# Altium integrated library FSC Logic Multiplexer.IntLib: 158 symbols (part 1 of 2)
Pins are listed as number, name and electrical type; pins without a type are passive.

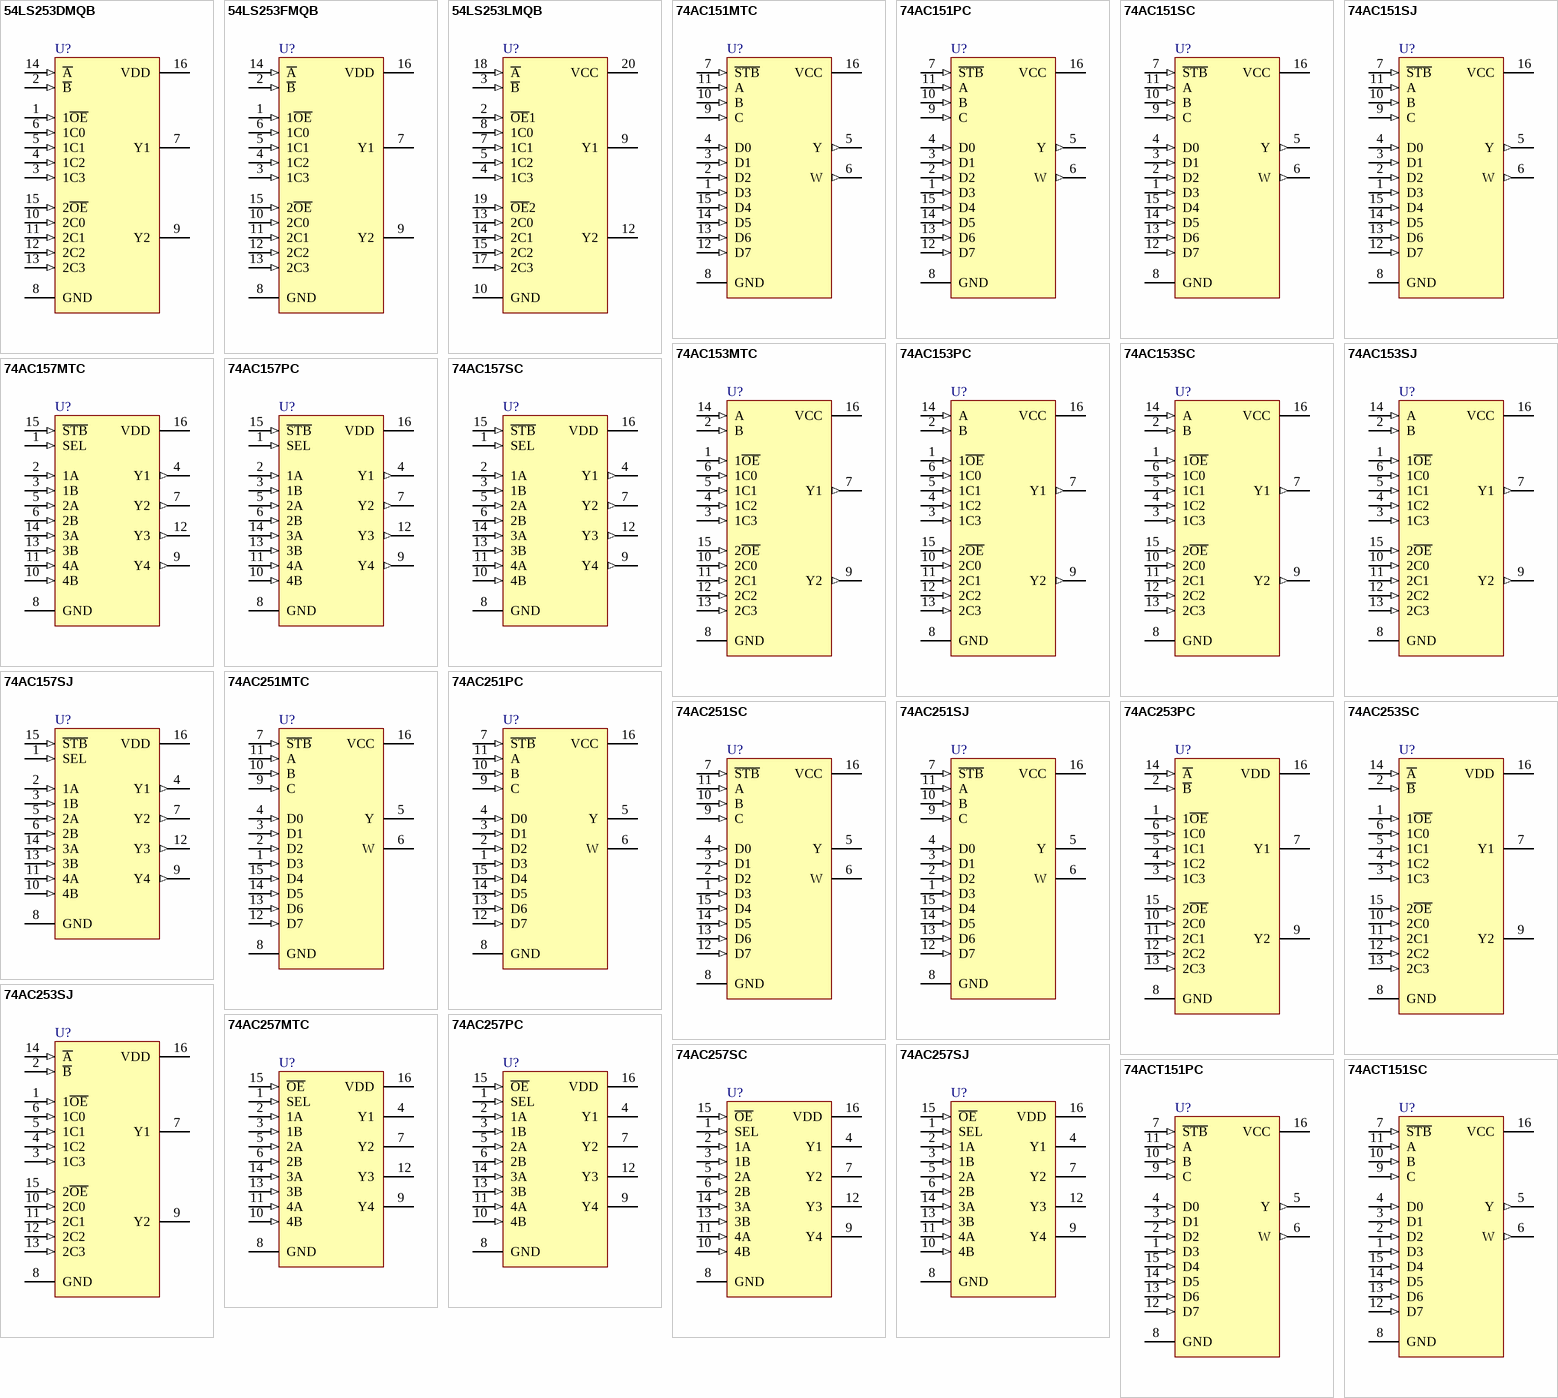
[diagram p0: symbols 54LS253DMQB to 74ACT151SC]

## 54LS253DMQB
designator U?
3-State Data Selector/Multiplexer; Note: Generic simulation model provided.
footprint J16A (DIP, 16-Leads, Row Spacing 7.62mm, Pitch 2.54mm, Body 19.56x6.73mm)
3D model N16E (CerDIP, 16-Pin, Row Spacing 7.62 mm, Pitch 2.54 mm)
simulation model 74LS253 (SIMCODE)
signal-integrity model 54LS253DMQB
pins: 1 1~{OE} (in), 2 ~{B} (in), 3 1C3 (in), 4 1C2 (in), 5 1C1 (in), 6 1C0 (in), 7 Y1 (hiz), 8 GND (power), 9 Y2 (hiz), 10 2C0 (in), 11 2C1 (in), 12 2C2 (in), 13 2C3 (in), 14 ~{A} (in), 15 2~{OE} (in), 16 VDD (power)

## 54LS253FMQB
designator U?
3-State Data Selector/Multiplexer; Note: Generic simulation model provided.
footprint W16A (DFP; 16 Leads; Body 9.9 x 7.6 mm (LxW max); Pitch 1.27 mm)
3D model W16A (DFP; 16 Leads; Body 9.9 x 7.6 mm (LxW max); Pitch 1.27 mm)
simulation model 74LS253 (SIMCODE)
signal-integrity model 54LS253FMQB
pins: 1 1~{OE} (in), 2 ~{B} (in), 3 1C3 (in), 4 1C2 (in), 5 1C1 (in), 6 1C0 (in), 7 Y1 (hiz), 8 GND (power), 9 Y2 (hiz), 10 2C0 (in), 11 2C1 (in), 12 2C2 (in), 13 2C3 (in), 14 ~{A} (in), 15 2~{OE} (in), 16 VDD (power)

## 54LS253LMQB
designator U?
3-State Data Selector/Multiplexer; Note: Pins 1, 6, 11 and 16 are not connected and not drawn.
footprint E20A (Leadless Chip Carrier; 20 Terminals; Body 8.9 x 8.9 mm)
footprint E20A_N (Leadless Chip Carrier, 20-Leads, Body 8.9x8.9mm, Pitch 1.27mm, IPC Medium Density)
footprint E20A_L (Leadless Chip Carrier, 20-Leads, Body 8.9x8.9mm, Pitch 1.27mm, IPC High Density)
footprint E20A_M (Leadless Chip Carrier, 20-Leads, Body 8.9x8.9mm, Pitch 1.27mm, IPC Low Density)
simulation model 74LS253 (SIMCODE)
signal-integrity model 54LS253LMQB
pins: 2 ~{OE}1 (in), 3 ~{B} (in), 4 1C3 (in), 5 1C2 (in), 7 1C1 (in), 8 1C0 (in), 9 Y1 (hiz), 10 GND (power), 12 Y2 (hiz), 13 2C0 (in), 14 2C1 (in), 15 2C2 (in), 17 2C3 (in), 18 ~{A} (in), 19 ~{OE}2 (in), 20 VCC (power)

## 74AC151MTC
designator U?
8-Input Multiplexer
footprint MTC16_N (TSOP, 16-Leads, Body 5x4.4mm, Pitch 0.65mm, IPC Medium Density)
footprint MTC16_L (TSOP, 16-Leads, Body 5x4.4mm, Pitch 0.65mm, IPC High Density)
footprint MTC16_M (TSOP, 16-Leads, Body 5x4.4mm, Pitch 0.65mm, IPC Low Density)
3D model MTC16 (16-Pin Thin Small Outline Package 0.65 mm Pitch)
signal-integrity model 74AC151MTC
pins: 1 D3 (in), 2 D2 (in), 3 D1 (in), 4 D0 (in), 5 Y (out), 6 W (out), 7 ~{STB} (in), 8 GND (power), 9 C (in), 10 B (in), 11 A (in), 12 D7 (in), 13 D6 (in), 14 D5 (in), 15 D4 (in), 16 VCC (power)

## 74AC151PC
designator U?
8-Input Multiplexer
footprint N16E (DIP, 16-Leads, Row Spacing 7.62mm, Pitch 2.54mm, Body 19.3x6.35mm)
3D model N16E (DIP, 16-Pin, Row Spacing 7.62 mm, Pitch 2.54 mm)
signal-integrity model 74AC151PC
pins: 1 D3 (in), 2 D2 (in), 3 D1 (in), 4 D0 (in), 5 Y (out), 6 W (out), 7 ~{STB} (in), 8 GND (power), 9 C (in), 10 B (in), 11 A (in), 12 D7 (in), 13 D6 (in), 14 D5 (in), 15 D4 (in), 16 VCC (power)

## 74AC151SC
designator U?
8-Input Multiplexer
footprint M16A_N (SOIC, 16-Leads, Body 9.9x3.9mm, Pitch 1.27mm, IPC Medium Density)
footprint M16A_L (SOIC, 16-Leads, Body 9.9x3.9mm, Pitch 1.27mm, IPC High Density)
footprint M16A_M (SOIC, 16-Leads, Body 9.9x3.9mm, Pitch 1.27mm, IPC Low Density)
3D model M16A (16-Pin Small Outline Integrated Circuit 1.27 mm Pitch)
signal-integrity model 74AC151SC
pins: 1 D3 (in), 2 D2 (in), 3 D1 (in), 4 D0 (in), 5 Y (out), 6 W (out), 7 ~{STB} (in), 8 GND (power), 9 C (in), 10 B (in), 11 A (in), 12 D7 (in), 13 D6 (in), 14 D5 (in), 15 D4 (in), 16 VCC (power)

## 74AC151SJ
designator U?
8-Input Multiplexer
footprint M16D_N (SOP, 16-Leads, Body 10.1x5.3mm, Pitch 1.27mm, IPC Medium Density)
footprint M16D_L (SOP, 16-Leads, Body 10.1x5.3mm, Pitch 1.27mm, IPC High Density)
footprint M16D_M (SOP, 16-Leads, Body 10.1x5.3mm, Pitch 1.27mm, IPC Low Density)
3D model M16D (16-Pin Small Outline Package 1.27 mm Pitch)
signal-integrity model 74AC151SJ
pins: 1 D3 (in), 2 D2 (in), 3 D1 (in), 4 D0 (in), 5 Y (out), 6 W (out), 7 ~{STB} (in), 8 GND (power), 9 C (in), 10 B (in), 11 A (in), 12 D7 (in), 13 D6 (in), 14 D5 (in), 15 D4 (in), 16 VCC (power)

## 74AC153MTC
designator U?
Dual 4-Input Multiplexer
footprint MTC16_N (TSOP, 16-Leads, Body 5x4.4mm, Pitch 0.65mm, IPC Medium Density)
footprint MTC16_L (TSOP, 16-Leads, Body 5x4.4mm, Pitch 0.65mm, IPC High Density)
footprint MTC16_M (TSOP, 16-Leads, Body 5x4.4mm, Pitch 0.65mm, IPC Low Density)
3D model MTC16 (16-Pin Thin Small Outline Package 0.65 mm Pitch)
signal-integrity model 74AC153MTC
pins: 1 1~{OE} (in), 2 B (in), 3 1C3 (in), 4 1C2 (in), 5 1C1 (in), 6 1C0 (in), 7 Y1 (out), 8 GND (power), 9 Y2 (out), 10 2C0 (in), 11 2C1 (in), 12 2C2 (in), 13 2C3 (in), 14 A (in), 15 2~{OE} (in), 16 VCC (power)

## 74AC153PC
designator U?
Dual 4-Input Multiplexer
footprint N16E (DIP, 16-Leads, Row Spacing 7.62mm, Pitch 2.54mm, Body 19.3x6.35mm)
3D model N16E (DIP, 16-Pin, Row Spacing 7.62 mm, Pitch 2.54 mm)
signal-integrity model 74AC153PC
pins: 1 1~{OE} (in), 2 B (in), 3 1C3 (in), 4 1C2 (in), 5 1C1 (in), 6 1C0 (in), 7 Y1 (out), 8 GND (power), 9 Y2 (out), 10 2C0 (in), 11 2C1 (in), 12 2C2 (in), 13 2C3 (in), 14 A (in), 15 2~{OE} (in), 16 VCC (power)

## 74AC153SC
designator U?
Dual 4-Input Multiplexer
footprint M16A_N (SOIC, 16-Leads, Body 9.9x3.9mm, Pitch 1.27mm, IPC Medium Density)
footprint M16A_L (SOIC, 16-Leads, Body 9.9x3.9mm, Pitch 1.27mm, IPC High Density)
footprint M16A_M (SOIC, 16-Leads, Body 9.9x3.9mm, Pitch 1.27mm, IPC Low Density)
3D model M16A (16-Pin Small Outline Integrated Circuit 1.27 mm Pitch)
signal-integrity model 74AC153SC
pins: 1 1~{OE} (in), 2 B (in), 3 1C3 (in), 4 1C2 (in), 5 1C1 (in), 6 1C0 (in), 7 Y1 (out), 8 GND (power), 9 Y2 (out), 10 2C0 (in), 11 2C1 (in), 12 2C2 (in), 13 2C3 (in), 14 A (in), 15 2~{OE} (in), 16 VCC (power)

## 74AC153SJ
designator U?
Dual 4-Input Multiplexer
footprint M16D_N (SOP, 16-Leads, Body 10.1x5.3mm, Pitch 1.27mm, IPC Medium Density)
footprint M16D_L (SOP, 16-Leads, Body 10.1x5.3mm, Pitch 1.27mm, IPC High Density)
footprint M16D_M (SOP, 16-Leads, Body 10.1x5.3mm, Pitch 1.27mm, IPC Low Density)
3D model M16D (16-Pin Small Outline Package 1.27 mm Pitch)
signal-integrity model 74AC153SJ
pins: 1 1~{OE} (in), 2 B (in), 3 1C3 (in), 4 1C2 (in), 5 1C1 (in), 6 1C0 (in), 7 Y1 (out), 8 GND (power), 9 Y2 (out), 10 2C0 (in), 11 2C1 (in), 12 2C2 (in), 13 2C3 (in), 14 A (in), 15 2~{OE} (in), 16 VCC (power)

## 74AC157MTC
designator U?
Quad 2-Input Multiplexer
footprint MTC16_N (TSOP, 16-Leads, Body 5x4.4mm, Pitch 0.65mm, IPC Medium Density)
footprint MTC16_L (TSOP, 16-Leads, Body 5x4.4mm, Pitch 0.65mm, IPC High Density)
footprint MTC16_M (TSOP, 16-Leads, Body 5x4.4mm, Pitch 0.65mm, IPC Low Density)
3D model MTC16 (16-Pin Thin Small Outline Package 0.65 mm Pitch)
signal-integrity model 74AC157MTC
pins: 1 SEL (in), 2 1A (in), 3 1B (in), 4 Y1 (out), 5 2A (in), 6 2B (in), 7 Y2 (out), 8 GND (power), 9 Y4 (out), 10 4B (in), 11 4A (in), 12 Y3 (out), 13 3B (in), 14 3A (in), 15 ~{STB} (in), 16 VDD (power)

## 74AC157PC
designator U?
Quad 2-Input Multiplexer
footprint N16E (DIP, 16-Leads, Row Spacing 7.62mm, Pitch 2.54mm, Body 19.3x6.35mm)
3D model N16E (DIP, 16-Pin, Row Spacing 7.62 mm, Pitch 2.54 mm)
signal-integrity model 74AC157PC
pins: 1 SEL (in), 2 1A (in), 3 1B (in), 4 Y1 (out), 5 2A (in), 6 2B (in), 7 Y2 (out), 8 GND (power), 9 Y4 (out), 10 4B (in), 11 4A (in), 12 Y3 (out), 13 3B (in), 14 3A (in), 15 ~{STB} (in), 16 VDD (power)

## 74AC157SC
designator U?
Quad 2-Input Multiplexer
footprint M16A_N (SOIC, 16-Leads, Body 9.9x3.9mm, Pitch 1.27mm, IPC Medium Density)
footprint M16A_L (SOIC, 16-Leads, Body 9.9x3.9mm, Pitch 1.27mm, IPC High Density)
footprint M16A_M (SOIC, 16-Leads, Body 9.9x3.9mm, Pitch 1.27mm, IPC Low Density)
3D model M16A (16-Pin Small Outline Integrated Circuit 1.27 mm Pitch)
signal-integrity model 74AC157SC
pins: 1 SEL (in), 2 1A (in), 3 1B (in), 4 Y1 (out), 5 2A (in), 6 2B (in), 7 Y2 (out), 8 GND (power), 9 Y4 (out), 10 4B (in), 11 4A (in), 12 Y3 (out), 13 3B (in), 14 3A (in), 15 ~{STB} (in), 16 VDD (power)

## 74AC157SJ
designator U?
Quad 2-Input Multiplexer
footprint M16D_N (SOP, 16-Leads, Body 10.1x5.3mm, Pitch 1.27mm, IPC Medium Density)
footprint M16D_L (SOP, 16-Leads, Body 10.1x5.3mm, Pitch 1.27mm, IPC High Density)
footprint M16D_M (SOP, 16-Leads, Body 10.1x5.3mm, Pitch 1.27mm, IPC Low Density)
3D model M16D (16-Pin Small Outline Package 1.27 mm Pitch)
signal-integrity model 74AC157SJ
pins: 1 SEL (in), 2 1A (in), 3 1B (in), 4 Y1 (out), 5 2A (in), 6 2B (in), 7 Y2 (out), 8 GND (power), 9 Y4 (out), 10 4B (in), 11 4A (in), 12 Y3 (out), 13 3B (in), 14 3A (in), 15 ~{STB} (in), 16 VDD (power)

## 74AC251MTC
designator U?
8-Input Multiplexer with 3-State Output; Note: Generic simulation model provided.
footprint MTC16_N (TSOP, 16-Leads, Body 5x4.4mm, Pitch 0.65mm, IPC Medium Density)
footprint MTC16_L (TSOP, 16-Leads, Body 5x4.4mm, Pitch 0.65mm, IPC High Density)
footprint MTC16_M (TSOP, 16-Leads, Body 5x4.4mm, Pitch 0.65mm, IPC Low Density)
3D model MTC16 (16-Pin Thin Small Outline Package 0.65 mm Pitch)
simulation model 74LS251 (SIMCODE)
signal-integrity model 74AC251MTC
pins: 1 D3 (in), 2 D2 (in), 3 D1 (in), 4 D0 (in), 5 Y (hiz), 6 W (hiz), 7 ~{STB} (in), 8 GND (power), 9 C (in), 10 B (in), 11 A (in), 12 D7 (in), 13 D6 (in), 14 D5 (in), 15 D4 (in), 16 VCC (power)

## 74AC251PC
designator U?
8-Input Multiplexer with 3-State Output; Note: Generic simulation model provided.
footprint N16E (DIP, 16-Leads, Row Spacing 7.62mm, Pitch 2.54mm, Body 19.3x6.35mm)
3D model N16E (DIP, 16-Pin, Row Spacing 7.62 mm, Pitch 2.54 mm)
simulation model 74LS251 (SIMCODE)
signal-integrity model 74AC251PC
pins: 1 D3 (in), 2 D2 (in), 3 D1 (in), 4 D0 (in), 5 Y (hiz), 6 W (hiz), 7 ~{STB} (in), 8 GND (power), 9 C (in), 10 B (in), 11 A (in), 12 D7 (in), 13 D6 (in), 14 D5 (in), 15 D4 (in), 16 VCC (power)

## 74AC251SC
designator U?
8-Input Multiplexer with 3-State Output; Note: Generic simulation model provided.
footprint M16A_N (SOIC, 16-Leads, Body 9.9x3.9mm, Pitch 1.27mm, IPC Medium Density)
footprint M16A_L (SOIC, 16-Leads, Body 9.9x3.9mm, Pitch 1.27mm, IPC High Density)
footprint M16A_M (SOIC, 16-Leads, Body 9.9x3.9mm, Pitch 1.27mm, IPC Low Density)
3D model M16A (16-Pin Small Outline Integrated Circuit 1.27 mm Pitch)
simulation model 74LS251 (SIMCODE)
signal-integrity model 74AC251SC
pins: 1 D3 (in), 2 D2 (in), 3 D1 (in), 4 D0 (in), 5 Y (hiz), 6 W (hiz), 7 ~{STB} (in), 8 GND (power), 9 C (in), 10 B (in), 11 A (in), 12 D7 (in), 13 D6 (in), 14 D5 (in), 15 D4 (in), 16 VCC (power)

## 74AC251SJ
designator U?
8-Input Multiplexer with 3-State Output; Note: Generic simulation model provided.
footprint M16D_N (SOP, 16-Leads, Body 10.1x5.3mm, Pitch 1.27mm, IPC Medium Density)
footprint M16D_L (SOP, 16-Leads, Body 10.1x5.3mm, Pitch 1.27mm, IPC High Density)
footprint M16D_M (SOP, 16-Leads, Body 10.1x5.3mm, Pitch 1.27mm, IPC Low Density)
3D model M16D (16-Pin Small Outline Package 1.27 mm Pitch)
simulation model 74LS251 (SIMCODE)
signal-integrity model 74AC251SJ
pins: 1 D3 (in), 2 D2 (in), 3 D1 (in), 4 D0 (in), 5 Y (hiz), 6 W (hiz), 7 ~{STB} (in), 8 GND (power), 9 C (in), 10 B (in), 11 A (in), 12 D7 (in), 13 D6 (in), 14 D5 (in), 15 D4 (in), 16 VCC (power)

## 74AC253PC
designator U?
Dual 4-Input Multiplexer with 3-State Outputs
footprint N16E (DIP, 16-Leads, Row Spacing 7.62mm, Pitch 2.54mm, Body 19.3x6.35mm)
3D model N16E (DIP, 16-Pin, Row Spacing 7.62 mm, Pitch 2.54 mm)
signal-integrity model 74AC253PC
pins: 1 1~{OE} (in), 2 ~{B} (in), 3 1C3 (in), 4 1C2 (in), 5 1C1 (in), 6 1C0 (in), 7 Y1 (hiz), 8 GND (power), 9 Y2 (hiz), 10 2C0 (in), 11 2C1 (in), 12 2C2 (in), 13 2C3 (in), 14 ~{A} (in), 15 2~{OE} (in), 16 VDD (power)

## 74AC253SC
designator U?
Dual 4-Input Multiplexer with 3-State Outputs
footprint M16A_N (SOIC, 16-Leads, Body 9.9x3.9mm, Pitch 1.27mm, IPC Medium Density)
footprint M16A_L (SOIC, 16-Leads, Body 9.9x3.9mm, Pitch 1.27mm, IPC High Density)
footprint M16A_M (SOIC, 16-Leads, Body 9.9x3.9mm, Pitch 1.27mm, IPC Low Density)
3D model M16A (16-Pin Small Outline Integrated Circuit 1.27 mm Pitch)
signal-integrity model 74AC253SC
pins: 1 1~{OE} (in), 2 ~{B} (in), 3 1C3 (in), 4 1C2 (in), 5 1C1 (in), 6 1C0 (in), 7 Y1 (hiz), 8 GND (power), 9 Y2 (hiz), 10 2C0 (in), 11 2C1 (in), 12 2C2 (in), 13 2C3 (in), 14 ~{A} (in), 15 2~{OE} (in), 16 VDD (power)

## 74AC253SJ
designator U?
Dual 4-Input Multiplexer with 3-State Outputs
footprint M16D_N (SOP, 16-Leads, Body 10.1x5.3mm, Pitch 1.27mm, IPC Medium Density)
footprint M16D_L (SOP, 16-Leads, Body 10.1x5.3mm, Pitch 1.27mm, IPC High Density)
footprint M16D_M (SOP, 16-Leads, Body 10.1x5.3mm, Pitch 1.27mm, IPC Low Density)
3D model M16D (16-Pin Small Outline Package 1.27 mm Pitch)
signal-integrity model 74AC253SJ
pins: 1 1~{OE} (in), 2 ~{B} (in), 3 1C3 (in), 4 1C2 (in), 5 1C1 (in), 6 1C0 (in), 7 Y1 (hiz), 8 GND (power), 9 Y2 (hiz), 10 2C0 (in), 11 2C1 (in), 12 2C2 (in), 13 2C3 (in), 14 ~{A} (in), 15 2~{OE} (in), 16 VDD (power)

## 74AC257MTC
designator U?
Quad 2-Input Multiplexer with 3-State Outputs
footprint MTC16_N (TSOP, 16-Leads, Body 5x4.4mm, Pitch 0.65mm, IPC Medium Density)
footprint MTC16_L (TSOP, 16-Leads, Body 5x4.4mm, Pitch 0.65mm, IPC High Density)
footprint MTC16_M (TSOP, 16-Leads, Body 5x4.4mm, Pitch 0.65mm, IPC Low Density)
3D model MTC16 (16-Pin Thin Small Outline Package 0.65 mm Pitch)
signal-integrity model 74AC257MTC
pins: 1 SEL (in), 2 1A (in), 3 1B (in), 4 Y1 (hiz), 5 2A (in), 6 2B (in), 7 Y2 (hiz), 8 GND (power), 9 Y4 (hiz), 10 4B (in), 11 4A (in), 12 Y3 (hiz), 13 3B (in), 14 3A (in), 15 ~{OE} (in), 16 VDD (power)

## 74AC257PC
designator U?
Quad 2-Input Multiplexer with 3-State Outputs
footprint N16E (DIP, 16-Leads, Row Spacing 7.62mm, Pitch 2.54mm, Body 19.3x6.35mm)
3D model N16E (DIP, 16-Pin, Row Spacing 7.62 mm, Pitch 2.54 mm)
signal-integrity model 74AC257PC
pins: 1 SEL (in), 2 1A (in), 3 1B (in), 4 Y1 (hiz), 5 2A (in), 6 2B (in), 7 Y2 (hiz), 8 GND (power), 9 Y4 (hiz), 10 4B (in), 11 4A (in), 12 Y3 (hiz), 13 3B (in), 14 3A (in), 15 ~{OE} (in), 16 VDD (power)

## 74AC257SC
designator U?
Quad 2-Input Multiplexer with 3-State Outputs
footprint M16A_N (SOIC, 16-Leads, Body 9.9x3.9mm, Pitch 1.27mm, IPC Medium Density)
footprint M16A_L (SOIC, 16-Leads, Body 9.9x3.9mm, Pitch 1.27mm, IPC High Density)
footprint M16A_M (SOIC, 16-Leads, Body 9.9x3.9mm, Pitch 1.27mm, IPC Low Density)
3D model M16A (16-Pin Small Outline Integrated Circuit 1.27 mm Pitch)
signal-integrity model 74AC257SC
pins: 1 SEL (in), 2 1A (in), 3 1B (in), 4 Y1 (hiz), 5 2A (in), 6 2B (in), 7 Y2 (hiz), 8 GND (power), 9 Y4 (hiz), 10 4B (in), 11 4A (in), 12 Y3 (hiz), 13 3B (in), 14 3A (in), 15 ~{OE} (in), 16 VDD (power)

## 74AC257SJ
designator U?
Quad 2-Input Multiplexer with 3-State Outputs
footprint M16D_N (SOP, 16-Leads, Body 10.1x5.3mm, Pitch 1.27mm, IPC Medium Density)
footprint M16D_L (SOP, 16-Leads, Body 10.1x5.3mm, Pitch 1.27mm, IPC High Density)
footprint M16D_M (SOP, 16-Leads, Body 10.1x5.3mm, Pitch 1.27mm, IPC Low Density)
3D model M16D (16-Pin Small Outline Package 1.27 mm Pitch)
signal-integrity model 74AC257SJ
pins: 1 SEL (in), 2 1A (in), 3 1B (in), 4 Y1 (hiz), 5 2A (in), 6 2B (in), 7 Y2 (hiz), 8 GND (power), 9 Y4 (hiz), 10 4B (in), 11 4A (in), 12 Y3 (hiz), 13 3B (in), 14 3A (in), 15 ~{OE} (in), 16 VDD (power)

## 74ACT151PC
designator U?
8-Input Multiplexer
footprint N16E (DIP, 16-Leads, Row Spacing 7.62mm, Pitch 2.54mm, Body 19.3x6.35mm)
3D model N16E (DIP, 16-Pin, Row Spacing 7.62 mm, Pitch 2.54 mm)
signal-integrity model 74ACT151PC
pins: 1 D3 (in), 2 D2 (in), 3 D1 (in), 4 D0 (in), 5 Y (out), 6 W (out), 7 ~{STB} (in), 8 GND (power), 9 C (in), 10 B (in), 11 A (in), 12 D7 (in), 13 D6 (in), 14 D5 (in), 15 D4 (in), 16 VCC (power)

## 74ACT151SC
designator U?
8-Input Multiplexer
footprint M16A_N (SOIC, 16-Leads, Body 9.9x3.9mm, Pitch 1.27mm, IPC Medium Density)
footprint M16A_L (SOIC, 16-Leads, Body 9.9x3.9mm, Pitch 1.27mm, IPC High Density)
footprint M16A_M (SOIC, 16-Leads, Body 9.9x3.9mm, Pitch 1.27mm, IPC Low Density)
3D model M16A (16-Pin Small Outline Integrated Circuit 1.27 mm Pitch)
signal-integrity model 74ACT151SC
pins: 1 D3 (in), 2 D2 (in), 3 D1 (in), 4 D0 (in), 5 Y (out), 6 W (out), 7 ~{STB} (in), 8 GND (power), 9 C (in), 10 B (in), 11 A (in), 12 D7 (in), 13 D6 (in), 14 D5 (in), 15 D4 (in), 16 VCC (power)

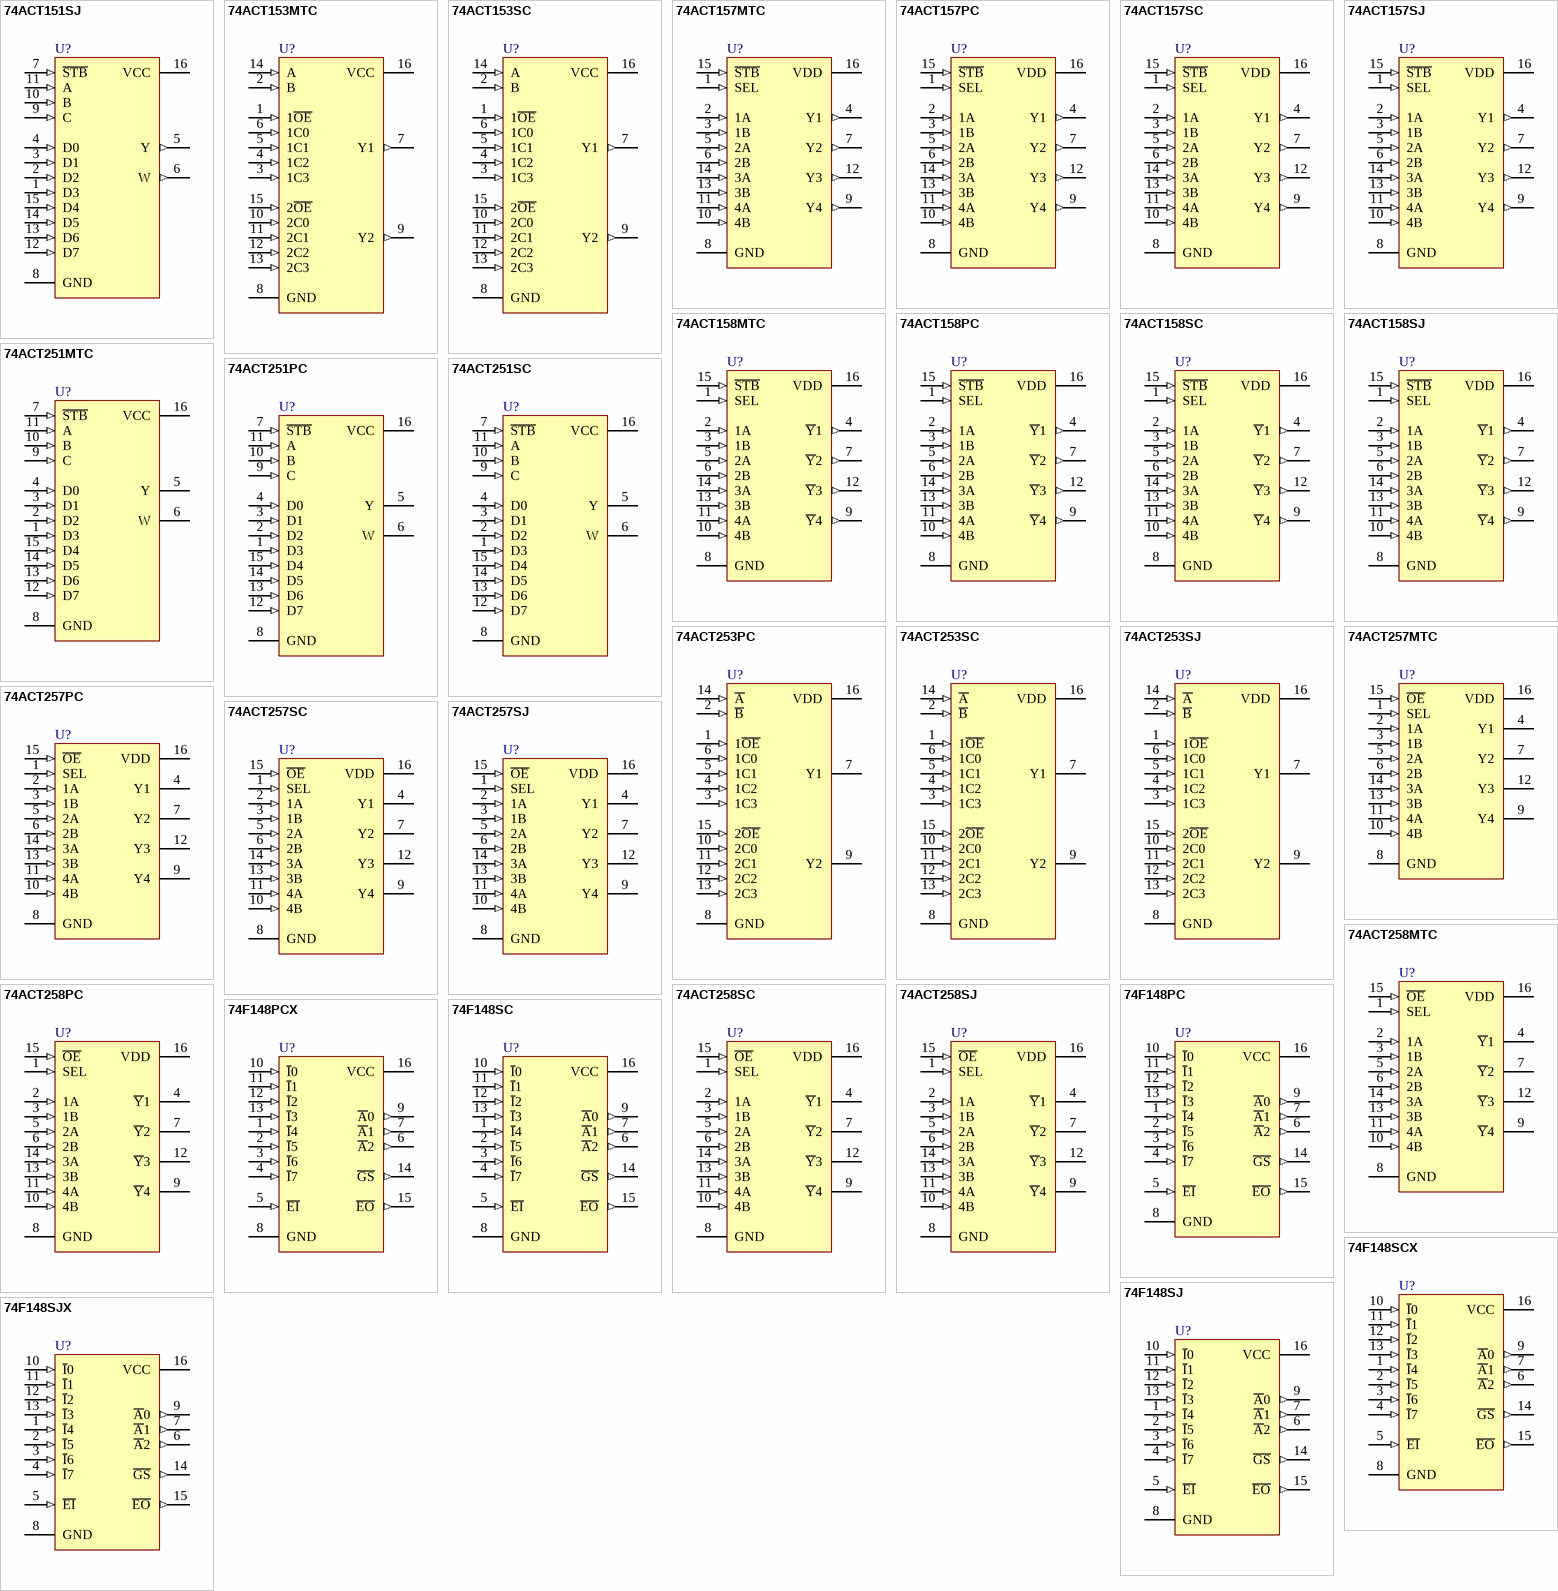
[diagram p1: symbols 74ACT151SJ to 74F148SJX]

## 74ACT151SJ
designator U?
8-Input Multiplexer
footprint M16D_N (SOP, 16-Leads, Body 10.1x5.3mm, Pitch 1.27mm, IPC Medium Density)
footprint M16D_L (SOP, 16-Leads, Body 10.1x5.3mm, Pitch 1.27mm, IPC High Density)
footprint M16D_M (SOP, 16-Leads, Body 10.1x5.3mm, Pitch 1.27mm, IPC Low Density)
3D model M16D (16-Pin Small Outline Package 1.27 mm Pitch)
signal-integrity model 74ACT151SJ
pins: 1 D3 (in), 2 D2 (in), 3 D1 (in), 4 D0 (in), 5 Y (out), 6 W (out), 7 ~{STB} (in), 8 GND (power), 9 C (in), 10 B (in), 11 A (in), 12 D7 (in), 13 D6 (in), 14 D5 (in), 15 D4 (in), 16 VCC (power)

## 74ACT153MTC
designator U?
Dual 4-Input Multiplexer
footprint MTC16_N (TSOP, 16-Leads, Body 5x4.4mm, Pitch 0.65mm, IPC Medium Density)
footprint MTC16_L (TSOP, 16-Leads, Body 5x4.4mm, Pitch 0.65mm, IPC High Density)
footprint MTC16_M (TSOP, 16-Leads, Body 5x4.4mm, Pitch 0.65mm, IPC Low Density)
3D model MTC16 (16-Pin Thin Small Outline Package 0.65 mm Pitch)
signal-integrity model 74ACT153MTC
pins: 1 1~{OE} (in), 2 B (in), 3 1C3 (in), 4 1C2 (in), 5 1C1 (in), 6 1C0 (in), 7 Y1 (out), 8 GND (power), 9 Y2 (out), 10 2C0 (in), 11 2C1 (in), 12 2C2 (in), 13 2C3 (in), 14 A (in), 15 2~{OE} (in), 16 VCC (power)

## 74ACT153SC
designator U?
Dual 4-Input Multiplexer
footprint M16A_N (SOIC, 16-Leads, Body 9.9x3.9mm, Pitch 1.27mm, IPC Medium Density)
footprint M16A_L (SOIC, 16-Leads, Body 9.9x3.9mm, Pitch 1.27mm, IPC High Density)
footprint M16A_M (SOIC, 16-Leads, Body 9.9x3.9mm, Pitch 1.27mm, IPC Low Density)
3D model M16A (16-Pin Small Outline Integrated Circuit 1.27 mm Pitch)
signal-integrity model 74ACT153SC
pins: 1 1~{OE} (in), 2 B (in), 3 1C3 (in), 4 1C2 (in), 5 1C1 (in), 6 1C0 (in), 7 Y1 (out), 8 GND (power), 9 Y2 (out), 10 2C0 (in), 11 2C1 (in), 12 2C2 (in), 13 2C3 (in), 14 A (in), 15 2~{OE} (in), 16 VCC (power)

## 74ACT157MTC
designator U?
Quad 2-Input Multiplexer
footprint MTC16_N (TSOP, 16-Leads, Body 5x4.4mm, Pitch 0.65mm, IPC Medium Density)
footprint MTC16_L (TSOP, 16-Leads, Body 5x4.4mm, Pitch 0.65mm, IPC High Density)
footprint MTC16_M (TSOP, 16-Leads, Body 5x4.4mm, Pitch 0.65mm, IPC Low Density)
3D model MTC16 (16-Pin Thin Small Outline Package 0.65 mm Pitch)
signal-integrity model 74ACT157MTC
pins: 1 SEL (in), 2 1A (in), 3 1B (in), 4 Y1 (out), 5 2A (in), 6 2B (in), 7 Y2 (out), 8 GND (power), 9 Y4 (out), 10 4B (in), 11 4A (in), 12 Y3 (out), 13 3B (in), 14 3A (in), 15 ~{STB} (in), 16 VDD (power)

## 74ACT157PC
designator U?
Quad 2-Input Multiplexer
footprint N16E (DIP, 16-Leads, Row Spacing 7.62mm, Pitch 2.54mm, Body 19.3x6.35mm)
3D model N16E (DIP, 16-Pin, Row Spacing 7.62 mm, Pitch 2.54 mm)
signal-integrity model 74ACT157PC
pins: 1 SEL (in), 2 1A (in), 3 1B (in), 4 Y1 (out), 5 2A (in), 6 2B (in), 7 Y2 (out), 8 GND (power), 9 Y4 (out), 10 4B (in), 11 4A (in), 12 Y3 (out), 13 3B (in), 14 3A (in), 15 ~{STB} (in), 16 VDD (power)

## 74ACT157SC
designator U?
Quad 2-Input Multiplexer
footprint M16A_N (SOIC, 16-Leads, Body 9.9x3.9mm, Pitch 1.27mm, IPC Medium Density)
footprint M16A_L (SOIC, 16-Leads, Body 9.9x3.9mm, Pitch 1.27mm, IPC High Density)
footprint M16A_M (SOIC, 16-Leads, Body 9.9x3.9mm, Pitch 1.27mm, IPC Low Density)
3D model M16A (16-Pin Small Outline Integrated Circuit 1.27 mm Pitch)
signal-integrity model 74ACT157SC
pins: 1 SEL (in), 2 1A (in), 3 1B (in), 4 Y1 (out), 5 2A (in), 6 2B (in), 7 Y2 (out), 8 GND (power), 9 Y4 (out), 10 4B (in), 11 4A (in), 12 Y3 (out), 13 3B (in), 14 3A (in), 15 ~{STB} (in), 16 VDD (power)

## 74ACT157SJ
designator U?
Quad 2-Input Multiplexer
footprint M16D_N (SOP, 16-Leads, Body 10.1x5.3mm, Pitch 1.27mm, IPC Medium Density)
footprint M16D_L (SOP, 16-Leads, Body 10.1x5.3mm, Pitch 1.27mm, IPC High Density)
footprint M16D_M (SOP, 16-Leads, Body 10.1x5.3mm, Pitch 1.27mm, IPC Low Density)
3D model M16D (16-Pin Small Outline Package 1.27 mm Pitch)
signal-integrity model 74ACT157SJ
pins: 1 SEL (in), 2 1A (in), 3 1B (in), 4 Y1 (out), 5 2A (in), 6 2B (in), 7 Y2 (out), 8 GND (power), 9 Y4 (out), 10 4B (in), 11 4A (in), 12 Y3 (out), 13 3B (in), 14 3A (in), 15 ~{STB} (in), 16 VDD (power)

## 74ACT158MTC
designator U?
Quad 2-Input Multiplexer; Note: Generic simulation model provided.
footprint MTC16_N (TSOP, 16-Leads, Body 5x4.4mm, Pitch 0.65mm, IPC Medium Density)
footprint MTC16_L (TSOP, 16-Leads, Body 5x4.4mm, Pitch 0.65mm, IPC High Density)
footprint MTC16_M (TSOP, 16-Leads, Body 5x4.4mm, Pitch 0.65mm, IPC Low Density)
3D model MTC16 (16-Pin Thin Small Outline Package 0.65 mm Pitch)
simulation model 74LS158 (SIMCODE)
signal-integrity model 74ACT158MTC
pins: 1 SEL (in), 2 1A (in), 3 1B (in), 4 ~{Y}1 (out), 5 2A (in), 6 2B (in), 7 ~{Y}2 (out), 8 GND (power), 9 ~{Y}4 (out), 10 4B (in), 11 4A (in), 12 ~{Y}3 (out), 13 3B (in), 14 3A (in), 15 ~{STB} (in), 16 VDD (power)

## 74ACT158PC
designator U?
Quad 2-Input Multiplexer; Note: Generic simulation model provided.
footprint M16D_N (SOP, 16-Leads, Body 10.1x5.3mm, Pitch 1.27mm, IPC Medium Density)
footprint M16D_L (SOP, 16-Leads, Body 10.1x5.3mm, Pitch 1.27mm, IPC High Density)
footprint M16D_M (SOP, 16-Leads, Body 10.1x5.3mm, Pitch 1.27mm, IPC Low Density)
3D model M16D (16-Pin Small Outline Package 1.27 mm Pitch)
simulation model 74LS158 (SIMCODE)
signal-integrity model 74ACT158PC
pins: 1 SEL (in), 2 1A (in), 3 1B (in), 4 ~{Y}1 (out), 5 2A (in), 6 2B (in), 7 ~{Y}2 (out), 8 GND (power), 9 ~{Y}4 (out), 10 4B (in), 11 4A (in), 12 ~{Y}3 (out), 13 3B (in), 14 3A (in), 15 ~{STB} (in), 16 VDD (power)

## 74ACT158SC
designator U?
Quad 2-Input Multiplexer; Note: Generic simulation model provided.
footprint M16A_N (SOIC, 16-Leads, Body 9.9x3.9mm, Pitch 1.27mm, IPC Medium Density)
footprint M16A_L (SOIC, 16-Leads, Body 9.9x3.9mm, Pitch 1.27mm, IPC High Density)
footprint M16A_M (SOIC, 16-Leads, Body 9.9x3.9mm, Pitch 1.27mm, IPC Low Density)
3D model M16A (16-Pin Small Outline Integrated Circuit 1.27 mm Pitch)
simulation model 74LS158 (SIMCODE)
signal-integrity model 74ACT158SC
pins: 1 SEL (in), 2 1A (in), 3 1B (in), 4 ~{Y}1 (out), 5 2A (in), 6 2B (in), 7 ~{Y}2 (out), 8 GND (power), 9 ~{Y}4 (out), 10 4B (in), 11 4A (in), 12 ~{Y}3 (out), 13 3B (in), 14 3A (in), 15 ~{STB} (in), 16 VDD (power)

## 74ACT158SJ
designator U?
Quad 2-Input Multiplexer; Note: Generic simulation model provided.
footprint N16E (DIP, 16-Leads, Row Spacing 7.62mm, Pitch 2.54mm, Body 19.3x6.35mm)
3D model N16E (DIP, 16-Pin, Row Spacing 7.62 mm, Pitch 2.54 mm)
simulation model 74LS158 (SIMCODE)
signal-integrity model 74ACT158SJ
pins: 1 SEL (in), 2 1A (in), 3 1B (in), 4 ~{Y}1 (out), 5 2A (in), 6 2B (in), 7 ~{Y}2 (out), 8 GND (power), 9 ~{Y}4 (out), 10 4B (in), 11 4A (in), 12 ~{Y}3 (out), 13 3B (in), 14 3A (in), 15 ~{STB} (in), 16 VDD (power)

## 74ACT251MTC
designator U?
8-Input Multiplexer with 3-State Output; Note: Generic simulation model provided.
footprint MTC16_N (TSOP, 16-Leads, Body 5x4.4mm, Pitch 0.65mm, IPC Medium Density)
footprint MTC16_L (TSOP, 16-Leads, Body 5x4.4mm, Pitch 0.65mm, IPC High Density)
footprint MTC16_M (TSOP, 16-Leads, Body 5x4.4mm, Pitch 0.65mm, IPC Low Density)
3D model MTC16 (16-Pin Thin Small Outline Package 0.65 mm Pitch)
simulation model 74LS251 (SIMCODE)
signal-integrity model 74ACT251MTC
pins: 1 D3 (in), 2 D2 (in), 3 D1 (in), 4 D0 (in), 5 Y (hiz), 6 W (hiz), 7 ~{STB} (in), 8 GND (power), 9 C (in), 10 B (in), 11 A (in), 12 D7 (in), 13 D6 (in), 14 D5 (in), 15 D4 (in), 16 VCC (power)

## 74ACT251PC
designator U?
8-Input Multiplexer with 3-State Output; Note: Generic simulation model provided.
footprint N16E (DIP, 16-Leads, Row Spacing 7.62mm, Pitch 2.54mm, Body 19.3x6.35mm)
3D model N16E (DIP, 16-Pin, Row Spacing 7.62 mm, Pitch 2.54 mm)
simulation model 74LS251 (SIMCODE)
signal-integrity model 74ACT251PC
pins: 1 D3 (in), 2 D2 (in), 3 D1 (in), 4 D0 (in), 5 Y (hiz), 6 W (hiz), 7 ~{STB} (in), 8 GND (power), 9 C (in), 10 B (in), 11 A (in), 12 D7 (in), 13 D6 (in), 14 D5 (in), 15 D4 (in), 16 VCC (power)

## 74ACT251SC
designator U?
8-Input Multiplexer with 3-State Output; Note: Generic simulation model provided.
footprint M16A_N (SOIC, 16-Leads, Body 9.9x3.9mm, Pitch 1.27mm, IPC Medium Density)
footprint M16A_L (SOIC, 16-Leads, Body 9.9x3.9mm, Pitch 1.27mm, IPC High Density)
footprint M16A_M (SOIC, 16-Leads, Body 9.9x3.9mm, Pitch 1.27mm, IPC Low Density)
3D model M16A (16-Pin Small Outline Integrated Circuit 1.27 mm Pitch)
simulation model 74LS251 (SIMCODE)
signal-integrity model 74ACT251SC
pins: 1 D3 (in), 2 D2 (in), 3 D1 (in), 4 D0 (in), 5 Y (hiz), 6 W (hiz), 7 ~{STB} (in), 8 GND (power), 9 C (in), 10 B (in), 11 A (in), 12 D7 (in), 13 D6 (in), 14 D5 (in), 15 D4 (in), 16 VCC (power)

## 74ACT253PC
designator U?
Dual 4-Input Multiplexer with 3-State Outputs
footprint N16E (DIP, 16-Leads, Row Spacing 7.62mm, Pitch 2.54mm, Body 19.3x6.35mm)
3D model N16E (DIP, 16-Pin, Row Spacing 7.62 mm, Pitch 2.54 mm)
signal-integrity model 74ACT253PC
pins: 1 1~{OE} (in), 2 ~{B} (in), 3 1C3 (in), 4 1C2 (in), 5 1C1 (in), 6 1C0 (in), 7 Y1 (hiz), 8 GND (power), 9 Y2 (hiz), 10 2C0 (in), 11 2C1 (in), 12 2C2 (in), 13 2C3 (in), 14 ~{A} (in), 15 2~{OE} (in), 16 VDD (power)

## 74ACT253SC
designator U?
Dual 4-Input Multiplexer with 3-State Outputs
footprint M16A_N (SOIC, 16-Leads, Body 9.9x3.9mm, Pitch 1.27mm, IPC Medium Density)
footprint M16A_L (SOIC, 16-Leads, Body 9.9x3.9mm, Pitch 1.27mm, IPC High Density)
footprint M16A_M (SOIC, 16-Leads, Body 9.9x3.9mm, Pitch 1.27mm, IPC Low Density)
3D model M16A (16-Pin Small Outline Integrated Circuit 1.27 mm Pitch)
signal-integrity model 74ACT253SC
pins: 1 1~{OE} (in), 2 ~{B} (in), 3 1C3 (in), 4 1C2 (in), 5 1C1 (in), 6 1C0 (in), 7 Y1 (hiz), 8 GND (power), 9 Y2 (hiz), 10 2C0 (in), 11 2C1 (in), 12 2C2 (in), 13 2C3 (in), 14 ~{A} (in), 15 2~{OE} (in), 16 VDD (power)

## 74ACT253SJ
designator U?
Dual 4-Input Multiplexer with 3-State Outputs
footprint M16D_N (SOP, 16-Leads, Body 10.1x5.3mm, Pitch 1.27mm, IPC Medium Density)
footprint M16D_L (SOP, 16-Leads, Body 10.1x5.3mm, Pitch 1.27mm, IPC High Density)
footprint M16D_M (SOP, 16-Leads, Body 10.1x5.3mm, Pitch 1.27mm, IPC Low Density)
3D model M16D (16-Pin Small Outline Package 1.27 mm Pitch)
signal-integrity model 74ACT253SJ
pins: 1 1~{OE} (in), 2 ~{B} (in), 3 1C3 (in), 4 1C2 (in), 5 1C1 (in), 6 1C0 (in), 7 Y1 (hiz), 8 GND (power), 9 Y2 (hiz), 10 2C0 (in), 11 2C1 (in), 12 2C2 (in), 13 2C3 (in), 14 ~{A} (in), 15 2~{OE} (in), 16 VDD (power)

## 74ACT257MTC
designator U?
Quad 2-Input Multiplexer with 3-State Outputs
footprint MTC16_N (TSOP, 16-Leads, Body 5x4.4mm, Pitch 0.65mm, IPC Medium Density)
footprint MTC16_L (TSOP, 16-Leads, Body 5x4.4mm, Pitch 0.65mm, IPC High Density)
footprint MTC16_M (TSOP, 16-Leads, Body 5x4.4mm, Pitch 0.65mm, IPC Low Density)
3D model MTC16 (16-Pin Thin Small Outline Package 0.65 mm Pitch)
signal-integrity model 74ACT257MTC
pins: 1 SEL (in), 2 1A (in), 3 1B (in), 4 Y1 (hiz), 5 2A (in), 6 2B (in), 7 Y2 (hiz), 8 GND (power), 9 Y4 (hiz), 10 4B (in), 11 4A (in), 12 Y3 (hiz), 13 3B (in), 14 3A (in), 15 ~{OE} (in), 16 VDD (power)

## 74ACT257PC
designator U?
Quad 2-Input Multiplexer with 3-State Outputs
footprint N16E (DIP, 16-Leads, Row Spacing 7.62mm, Pitch 2.54mm, Body 19.3x6.35mm)
3D model N16E (DIP, 16-Pin, Row Spacing 7.62 mm, Pitch 2.54 mm)
signal-integrity model 74ACT257PC
pins: 1 SEL (in), 2 1A (in), 3 1B (in), 4 Y1 (hiz), 5 2A (in), 6 2B (in), 7 Y2 (hiz), 8 GND (power), 9 Y4 (hiz), 10 4B (in), 11 4A (in), 12 Y3 (hiz), 13 3B (in), 14 3A (in), 15 ~{OE} (in), 16 VDD (power)

## 74ACT257SC
designator U?
Quad 2-Input Multiplexer with 3-State Outputs
footprint M16A_N (SOIC, 16-Leads, Body 9.9x3.9mm, Pitch 1.27mm, IPC Medium Density)
footprint M16A_L (SOIC, 16-Leads, Body 9.9x3.9mm, Pitch 1.27mm, IPC High Density)
footprint M16A_M (SOIC, 16-Leads, Body 9.9x3.9mm, Pitch 1.27mm, IPC Low Density)
3D model M16A (16-Pin Small Outline Integrated Circuit 1.27 mm Pitch)
signal-integrity model 74ACT257SC
pins: 1 SEL (in), 2 1A (in), 3 1B (in), 4 Y1 (hiz), 5 2A (in), 6 2B (in), 7 Y2 (hiz), 8 GND (power), 9 Y4 (hiz), 10 4B (in), 11 4A (in), 12 Y3 (hiz), 13 3B (in), 14 3A (in), 15 ~{OE} (in), 16 VDD (power)

## 74ACT257SJ
designator U?
Quad 2-Input Multiplexer with 3-State Outputs
footprint M16D_N (SOP, 16-Leads, Body 10.1x5.3mm, Pitch 1.27mm, IPC Medium Density)
footprint M16D_L (SOP, 16-Leads, Body 10.1x5.3mm, Pitch 1.27mm, IPC High Density)
footprint M16D_M (SOP, 16-Leads, Body 10.1x5.3mm, Pitch 1.27mm, IPC Low Density)
3D model M16D (16-Pin Small Outline Package 1.27 mm Pitch)
signal-integrity model 74ACT257SJ
pins: 1 SEL (in), 2 1A (in), 3 1B (in), 4 Y1 (hiz), 5 2A (in), 6 2B (in), 7 Y2 (hiz), 8 GND (power), 9 Y4 (hiz), 10 4B (in), 11 4A (in), 12 Y3 (hiz), 13 3B (in), 14 3A (in), 15 ~{OE} (in), 16 VDD (power)

## 74ACT258MTC
designator U?
Quad 2-Input Multiplexer with 3-State Outputs
footprint MTC16_N (TSOP, 16-Leads, Body 5x4.4mm, Pitch 0.65mm, IPC Medium Density)
footprint MTC16_L (TSOP, 16-Leads, Body 5x4.4mm, Pitch 0.65mm, IPC High Density)
footprint MTC16_M (TSOP, 16-Leads, Body 5x4.4mm, Pitch 0.65mm, IPC Low Density)
3D model MTC16 (16-Pin Thin Small Outline Package 0.65 mm Pitch)
signal-integrity model 74ACT258MTC
pins: 1 SEL (in), 2 1A (in), 3 1B (in), 4 ~{Y}1 (hiz), 5 2A (in), 6 2B (in), 7 ~{Y}2 (hiz), 8 GND (power), 9 ~{Y}4 (hiz), 10 4B (in), 11 4A (in), 12 ~{Y}3 (hiz), 13 3B (in), 14 3A (in), 15 ~{OE} (in), 16 VDD (power)

## 74ACT258PC
designator U?
Quad 2-Input Multiplexer with 3-State Outputs
footprint N16E (DIP, 16-Leads, Row Spacing 7.62mm, Pitch 2.54mm, Body 19.3x6.35mm)
3D model N16E (DIP, 16-Pin, Row Spacing 7.62 mm, Pitch 2.54 mm)
signal-integrity model 74ACT258PC
pins: 1 SEL (in), 2 1A (in), 3 1B (in), 4 ~{Y}1 (hiz), 5 2A (in), 6 2B (in), 7 ~{Y}2 (hiz), 8 GND (power), 9 ~{Y}4 (hiz), 10 4B (in), 11 4A (in), 12 ~{Y}3 (hiz), 13 3B (in), 14 3A (in), 15 ~{OE} (in), 16 VDD (power)

## 74ACT258SC
designator U?
Quad 2-Input Multiplexer with 3-State Outputs
footprint M16A_N (SOIC, 16-Leads, Body 9.9x3.9mm, Pitch 1.27mm, IPC Medium Density)
footprint M16A_L (SOIC, 16-Leads, Body 9.9x3.9mm, Pitch 1.27mm, IPC High Density)
footprint M16A_M (SOIC, 16-Leads, Body 9.9x3.9mm, Pitch 1.27mm, IPC Low Density)
3D model M16A (16-Pin Small Outline Integrated Circuit 1.27 mm Pitch)
signal-integrity model 74ACT258SC
pins: 1 SEL (in), 2 1A (in), 3 1B (in), 4 ~{Y}1 (hiz), 5 2A (in), 6 2B (in), 7 ~{Y}2 (hiz), 8 GND (power), 9 ~{Y}4 (hiz), 10 4B (in), 11 4A (in), 12 ~{Y}3 (hiz), 13 3B (in), 14 3A (in), 15 ~{OE} (in), 16 VDD (power)

## 74ACT258SJ
designator U?
Quad 2-Input Multiplexer with 3-State Outputs
footprint M16D_N (SOP, 16-Leads, Body 10.1x5.3mm, Pitch 1.27mm, IPC Medium Density)
footprint M16D_L (SOP, 16-Leads, Body 10.1x5.3mm, Pitch 1.27mm, IPC High Density)
footprint M16D_M (SOP, 16-Leads, Body 10.1x5.3mm, Pitch 1.27mm, IPC Low Density)
3D model M16D (16-Pin Small Outline Package 1.27 mm Pitch)
signal-integrity model 74ACT258SJ
pins: 1 SEL (in), 2 1A (in), 3 1B (in), 4 ~{Y}1 (hiz), 5 2A (in), 6 2B (in), 7 ~{Y}2 (hiz), 8 GND (power), 9 ~{Y}4 (hiz), 10 4B (in), 11 4A (in), 12 ~{Y}3 (hiz), 13 3B (in), 14 3A (in), 15 ~{OE} (in), 16 VDD (power)

## 74F148PC
designator U?
8-Line to 3-Line Priority Encoder; Note: Generic simulation model provided.
footprint N16E (DIP, 16-Leads, Row Spacing 7.62mm, Pitch 2.54mm, Body 19.3x6.35mm)
3D model N16E (DIP, 16-Pin, Row Spacing 7.62 mm, Pitch 2.54 mm)
simulation model 74F148 (SIMCODE)
signal-integrity model 74F148PC
pins: 1 ~{I}4 (in), 2 ~{I}5 (in), 3 ~{I}6 (in), 4 ~{I}7 (in), 5 ~{EI} (in), 6 ~{A}2 (out), 7 ~{A}1 (out), 8 GND (power), 9 ~{A}0 (out), 10 ~{I}0 (in), 11 ~{I}1 (in), 12 ~{I}2 (in), 13 ~{I}3 (in), 14 ~{GS} (out), 15 ~{EO} (out), 16 VCC (power)

## 74F148PCX
designator U?
8-Line to 3-Line Priority Encoder; Note: Generic simulation model provided.
footprint N16E (DIP, 16-Leads, Row Spacing 7.62mm, Pitch 2.54mm, Body 19.3x6.35mm)
3D model N16E (DIP, 16-Pin, Row Spacing 7.62 mm, Pitch 2.54 mm)
simulation model 74F148 (SIMCODE)
signal-integrity model 74F148PCX
pins: 1 ~{I}4 (in), 2 ~{I}5 (in), 3 ~{I}6 (in), 4 ~{I}7 (in), 5 ~{EI} (in), 6 ~{A}2 (out), 7 ~{A}1 (out), 8 GND (power), 9 ~{A}0 (out), 10 ~{I}0 (in), 11 ~{I}1 (in), 12 ~{I}2 (in), 13 ~{I}3 (in), 14 ~{GS} (out), 15 ~{EO} (out), 16 VCC (power)

## 74F148SC
designator U?
8-Line to 3-Line Priority Encoder; Note: Generic simulation model provided.
footprint M16A_N (SOIC, 16-Leads, Body 9.9x3.9mm, Pitch 1.27mm, IPC Medium Density)
footprint M16A_L (SOIC, 16-Leads, Body 9.9x3.9mm, Pitch 1.27mm, IPC High Density)
footprint M16A_M (SOIC, 16-Leads, Body 9.9x3.9mm, Pitch 1.27mm, IPC Low Density)
3D model M16A (16-Pin Small Outline Integrated Circuit 1.27 mm Pitch)
simulation model 74F148 (SIMCODE)
signal-integrity model 74F148SC
pins: 1 ~{I}4 (in), 2 ~{I}5 (in), 3 ~{I}6 (in), 4 ~{I}7 (in), 5 ~{EI} (in), 6 ~{A}2 (out), 7 ~{A}1 (out), 8 GND (power), 9 ~{A}0 (out), 10 ~{I}0 (in), 11 ~{I}1 (in), 12 ~{I}2 (in), 13 ~{I}3 (in), 14 ~{GS} (out), 15 ~{EO} (out), 16 VCC (power)

## 74F148SCX
designator U?
8-Line to 3-Line Priority Encoder; Note: Generic simulation model provided.
footprint M16A_N (SOIC, 16-Leads, Body 9.9x3.9mm, Pitch 1.27mm, IPC Medium Density)
footprint M16A_L (SOIC, 16-Leads, Body 9.9x3.9mm, Pitch 1.27mm, IPC High Density)
footprint M16A_M (SOIC, 16-Leads, Body 9.9x3.9mm, Pitch 1.27mm, IPC Low Density)
3D model M16A (16-Pin Small Outline Integrated Circuit 1.27 mm Pitch)
simulation model 74F148 (SIMCODE)
signal-integrity model 74F148SCX
pins: 1 ~{I}4 (in), 2 ~{I}5 (in), 3 ~{I}6 (in), 4 ~{I}7 (in), 5 ~{EI} (in), 6 ~{A}2 (out), 7 ~{A}1 (out), 8 GND (power), 9 ~{A}0 (out), 10 ~{I}0 (in), 11 ~{I}1 (in), 12 ~{I}2 (in), 13 ~{I}3 (in), 14 ~{GS} (out), 15 ~{EO} (out), 16 VCC (power)

## 74F148SJ
designator U?
8-Line to 3-Line Priority Encoder; Note: Generic simulation model provided.
footprint M16D_N (SOP, 16-Leads, Body 10.1x5.3mm, Pitch 1.27mm, IPC Medium Density)
footprint M16D_L (SOP, 16-Leads, Body 10.1x5.3mm, Pitch 1.27mm, IPC High Density)
footprint M16D_M (SOP, 16-Leads, Body 10.1x5.3mm, Pitch 1.27mm, IPC Low Density)
3D model M16D (16-Pin Small Outline Package 1.27 mm Pitch)
simulation model 74F148 (SIMCODE)
signal-integrity model 74F148SJ
pins: 1 ~{I}4 (in), 2 ~{I}5 (in), 3 ~{I}6 (in), 4 ~{I}7 (in), 5 ~{EI} (in), 6 ~{A}2 (out), 7 ~{A}1 (out), 8 GND (power), 9 ~{A}0 (out), 10 ~{I}0 (in), 11 ~{I}1 (in), 12 ~{I}2 (in), 13 ~{I}3 (in), 14 ~{GS} (out), 15 ~{EO} (out), 16 VCC (power)

## 74F148SJX
designator U?
8-Line to 3-Line Priority Encoder; Note: Generic simulation model provided.
footprint M16D_N (SOP, 16-Leads, Body 10.1x5.3mm, Pitch 1.27mm, IPC Medium Density)
footprint M16D_L (SOP, 16-Leads, Body 10.1x5.3mm, Pitch 1.27mm, IPC High Density)
footprint M16D_M (SOP, 16-Leads, Body 10.1x5.3mm, Pitch 1.27mm, IPC Low Density)
3D model M16D (16-Pin Small Outline Package 1.27 mm Pitch)
simulation model 74F148 (SIMCODE)
signal-integrity model 74F148SJX
pins: 1 ~{I}4 (in), 2 ~{I}5 (in), 3 ~{I}6 (in), 4 ~{I}7 (in), 5 ~{EI} (in), 6 ~{A}2 (out), 7 ~{A}1 (out), 8 GND (power), 9 ~{A}0 (out), 10 ~{I}0 (in), 11 ~{I}1 (in), 12 ~{I}2 (in), 13 ~{I}3 (in), 14 ~{GS} (out), 15 ~{EO} (out), 16 VCC (power)

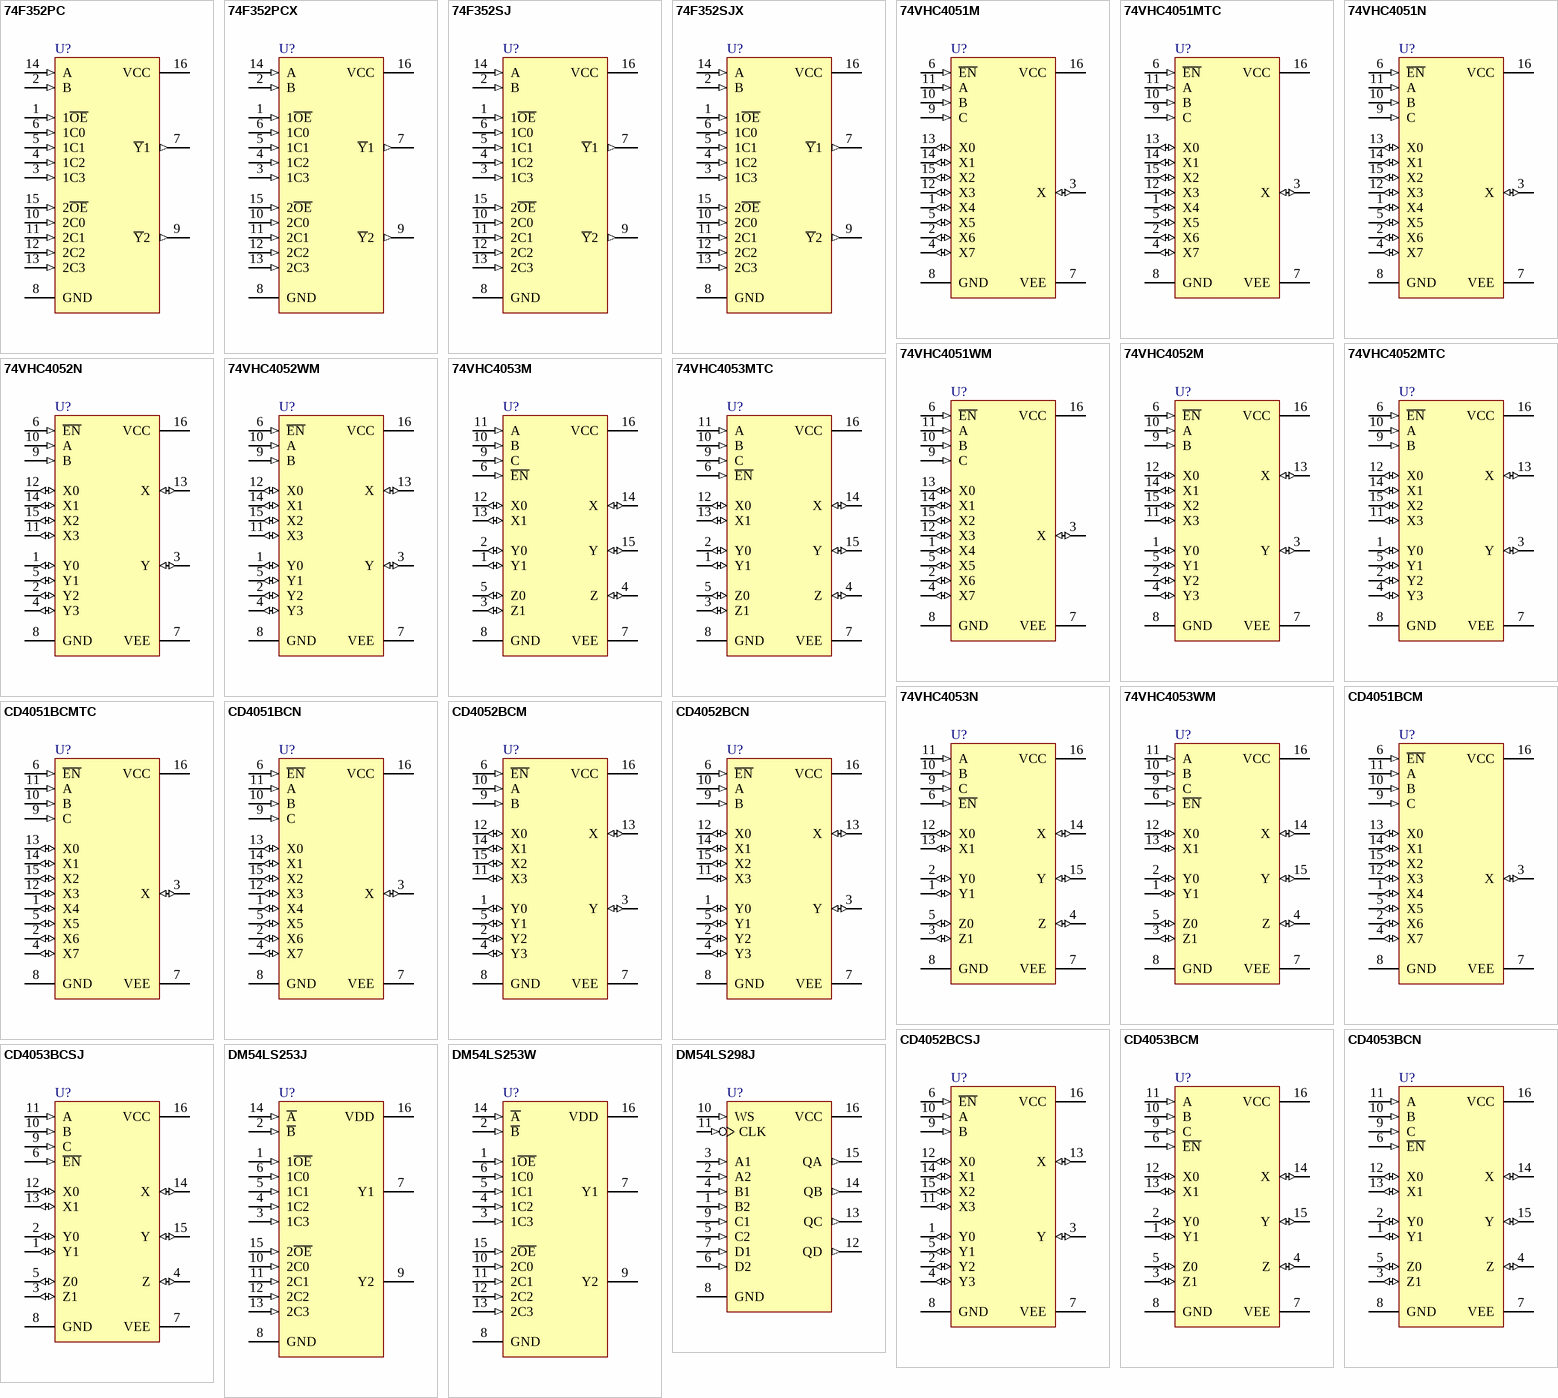
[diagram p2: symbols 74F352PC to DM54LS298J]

## 74F352PC
designator U?
Dual 4-Input Multiplexer; Note: Generic simulation model provided.
footprint N16E (DIP, 16-Leads, Row Spacing 7.62mm, Pitch 2.54mm, Body 19.3x6.35mm)
3D model N16E (DIP, 16-Pin, Row Spacing 7.62 mm, Pitch 2.54 mm)
simulation model 74F352 (SIMCODE)
signal-integrity model 74F352PC
pins: 1 1~{OE} (in), 2 B (in), 3 1C3 (in), 4 1C2 (in), 5 1C1 (in), 6 1C0 (in), 7 ~{Y}1 (out), 8 GND (power), 9 ~{Y}2 (out), 10 2C0 (in), 11 2C1 (in), 12 2C2 (in), 13 2C3 (in), 14 A (in), 15 2~{OE} (in), 16 VCC (power)

## 74F352PCX
designator U?
Dual 4-Input Multiplexer; Note: Generic simulation model provided.
footprint N16E (DIP, 16-Leads, Row Spacing 7.62mm, Pitch 2.54mm, Body 19.3x6.35mm)
3D model N16E (DIP, 16-Pin, Row Spacing 7.62 mm, Pitch 2.54 mm)
simulation model 74F352 (SIMCODE)
signal-integrity model 74F352PCX
pins: 1 1~{OE} (in), 2 B (in), 3 1C3 (in), 4 1C2 (in), 5 1C1 (in), 6 1C0 (in), 7 ~{Y}1 (out), 8 GND (power), 9 ~{Y}2 (out), 10 2C0 (in), 11 2C1 (in), 12 2C2 (in), 13 2C3 (in), 14 A (in), 15 2~{OE} (in), 16 VCC (power)

## 74F352SJ
designator U?
Dual 4-Input Multiplexer; Note: Generic simulation model provided.
footprint M16D_N (SOP, 16-Leads, Body 10.1x5.3mm, Pitch 1.27mm, IPC Medium Density)
footprint M16D_L (SOP, 16-Leads, Body 10.1x5.3mm, Pitch 1.27mm, IPC High Density)
footprint M16D_M (SOP, 16-Leads, Body 10.1x5.3mm, Pitch 1.27mm, IPC Low Density)
3D model M16D (16-Pin Small Outline Package 1.27 mm Pitch)
simulation model 74F352 (SIMCODE)
signal-integrity model 74F352SJ
pins: 1 1~{OE} (in), 2 B (in), 3 1C3 (in), 4 1C2 (in), 5 1C1 (in), 6 1C0 (in), 7 ~{Y}1 (out), 8 GND (power), 9 ~{Y}2 (out), 10 2C0 (in), 11 2C1 (in), 12 2C2 (in), 13 2C3 (in), 14 A (in), 15 2~{OE} (in), 16 VCC (power)

## 74F352SJX
designator U?
Dual 4-Input Multiplexer; Note: Generic simulation model provided.
footprint M16D_N (SOP, 16-Leads, Body 10.1x5.3mm, Pitch 1.27mm, IPC Medium Density)
footprint M16D_L (SOP, 16-Leads, Body 10.1x5.3mm, Pitch 1.27mm, IPC High Density)
footprint M16D_M (SOP, 16-Leads, Body 10.1x5.3mm, Pitch 1.27mm, IPC Low Density)
3D model M16D (16-Pin Small Outline Package 1.27 mm Pitch)
simulation model 74F352 (SIMCODE)
signal-integrity model 74F352SJX
pins: 1 1~{OE} (in), 2 B (in), 3 1C3 (in), 4 1C2 (in), 5 1C1 (in), 6 1C0 (in), 7 ~{Y}1 (out), 8 GND (power), 9 ~{Y}2 (out), 10 2C0 (in), 11 2C1 (in), 12 2C2 (in), 13 2C3 (in), 14 A (in), 15 2~{OE} (in), 16 VCC (power)

## 74VHC4051M
designator U?
8-Channel Analog Multiplexer
footprint M16A_N (SOIC, 16-Leads, Body 9.9x3.9mm, Pitch 1.27mm, IPC Medium Density)
footprint M16A_L (SOIC, 16-Leads, Body 9.9x3.9mm, Pitch 1.27mm, IPC High Density)
footprint M16A_M (SOIC, 16-Leads, Body 9.9x3.9mm, Pitch 1.27mm, IPC Low Density)
3D model M16A (16-Pin Small Outline Integrated Circuit 1.27 mm Pitch)
pins: 1 X4 (io), 2 X6 (io), 3 X (io), 4 X7 (io), 5 X5 (io), 6 ~{EN} (in), 7 VEE (power), 8 GND (power), 9 C (in), 10 B (in), 11 A (in), 12 X3 (io), 13 X0 (io), 14 X1 (io), 15 X2 (io), 16 VCC (power)

## 74VHC4051MTC
designator U?
8-Channel Analog Multiplexer
footprint MTC16_N (TSOP, 16-Leads, Body 5x4.4mm, Pitch 0.65mm, IPC Medium Density)
footprint MTC16_L (TSOP, 16-Leads, Body 5x4.4mm, Pitch 0.65mm, IPC High Density)
footprint MTC16_M (TSOP, 16-Leads, Body 5x4.4mm, Pitch 0.65mm, IPC Low Density)
3D model MTC16 (16-Pin Thin Small Outline Package 0.65 mm Pitch)
pins: 1 X4 (io), 2 X6 (io), 3 X (io), 4 X7 (io), 5 X5 (io), 6 ~{EN} (in), 7 VEE (power), 8 GND (power), 9 C (in), 10 B (in), 11 A (in), 12 X3 (io), 13 X0 (io), 14 X1 (io), 15 X2 (io), 16 VCC (power)

## 74VHC4051N
designator U?
8-Channel Analog Multiplexer
footprint N16E (DIP, 16-Leads, Row Spacing 7.62mm, Pitch 2.54mm, Body 19.3x6.35mm)
3D model N16E (DIP, 16-Pin, Row Spacing 7.62 mm, Pitch 2.54 mm)
pins: 1 X4 (io), 2 X6 (io), 3 X (io), 4 X7 (io), 5 X5 (io), 6 ~{EN} (in), 7 VEE (power), 8 GND (power), 9 C (in), 10 B (in), 11 A (in), 12 X3 (io), 13 X0 (io), 14 X1 (io), 15 X2 (io), 16 VCC (power)

## 74VHC4051WM
designator U?
8-Channel Analog Multiplexer
footprint M16B_N (SOIC, 16-Leads, Body 10.3x7.5mm, Pitch 1.27mm, IPC Medium Density)
footprint M16B_L (SOIC, 16-Leads, Body 10.3x7.5mm, Pitch 1.27mm, IPC High Density)
footprint M16B_M (SOIC, 16-Leads, Body 10.3x7.5mm, Pitch 1.27mm, IPC Low Density)
3D model M16B (16-Pin Small Outline Integrated Circuit 1.27 mm Pitch)
pins: 1 X4 (io), 2 X6 (io), 3 X (io), 4 X7 (io), 5 X5 (io), 6 ~{EN} (in), 7 VEE (power), 8 GND (power), 9 C (in), 10 B (in), 11 A (in), 12 X3 (io), 13 X0 (io), 14 X1 (io), 15 X2 (io), 16 VCC (power)

## 74VHC4052M
designator U?
Dual 4-Channel Analog Multiplexer
footprint M16A_N (SOIC, 16-Leads, Body 9.9x3.9mm, Pitch 1.27mm, IPC Medium Density)
footprint M16A_L (SOIC, 16-Leads, Body 9.9x3.9mm, Pitch 1.27mm, IPC High Density)
footprint M16A_M (SOIC, 16-Leads, Body 9.9x3.9mm, Pitch 1.27mm, IPC Low Density)
3D model M16A (16-Pin Small Outline Integrated Circuit 1.27 mm Pitch)
pins: 1 Y0 (io), 2 Y2 (io), 3 Y (io), 4 Y3 (io), 5 Y1 (io), 6 ~{EN} (in), 7 VEE (power), 8 GND (power), 9 B (in), 10 A (in), 11 X3 (io), 12 X0 (io), 13 X (io), 14 X1 (io), 15 X2 (io), 16 VCC (power)

## 74VHC4052MTC
designator U?
Dual 4-Channel Analog Multiplexer
footprint MTC16_N (TSOP, 16-Leads, Body 5x4.4mm, Pitch 0.65mm, IPC Medium Density)
footprint MTC16_L (TSOP, 16-Leads, Body 5x4.4mm, Pitch 0.65mm, IPC High Density)
footprint MTC16_M (TSOP, 16-Leads, Body 5x4.4mm, Pitch 0.65mm, IPC Low Density)
3D model MTC16 (16-Pin Thin Small Outline Package 0.65 mm Pitch)
pins: 1 Y0 (io), 2 Y2 (io), 3 Y (io), 4 Y3 (io), 5 Y1 (io), 6 ~{EN} (in), 7 VEE (power), 8 GND (power), 9 B (in), 10 A (in), 11 X3 (io), 12 X0 (io), 13 X (io), 14 X1 (io), 15 X2 (io), 16 VCC (power)

## 74VHC4052N
designator U?
Dual 4-Channel Analog Multiplexer
footprint N16E (DIP, 16-Leads, Row Spacing 7.62mm, Pitch 2.54mm, Body 19.3x6.35mm)
3D model N16E (DIP, 16-Pin, Row Spacing 7.62 mm, Pitch 2.54 mm)
pins: 1 Y0 (io), 2 Y2 (io), 3 Y (io), 4 Y3 (io), 5 Y1 (io), 6 ~{EN} (in), 7 VEE (power), 8 GND (power), 9 B (in), 10 A (in), 11 X3 (io), 12 X0 (io), 13 X (io), 14 X1 (io), 15 X2 (io), 16 VCC (power)

## 74VHC4052WM
designator U?
Dual 4-Channel Analog Multiplexer
footprint M16B_N (SOIC, 16-Leads, Body 10.3x7.5mm, Pitch 1.27mm, IPC Medium Density)
footprint M16B_L (SOIC, 16-Leads, Body 10.3x7.5mm, Pitch 1.27mm, IPC High Density)
footprint M16B_M (SOIC, 16-Leads, Body 10.3x7.5mm, Pitch 1.27mm, IPC Low Density)
3D model M16B (16-Pin Small Outline Integrated Circuit 1.27 mm Pitch)
pins: 1 Y0 (io), 2 Y2 (io), 3 Y (io), 4 Y3 (io), 5 Y1 (io), 6 ~{EN} (in), 7 VEE (power), 8 GND (power), 9 B (in), 10 A (in), 11 X3 (io), 12 X0 (io), 13 X (io), 14 X1 (io), 15 X2 (io), 16 VCC (power)

## 74VHC4053M
designator U?
Triple 2-Channnel Analog Multiplexer
footprint M16A_N (SOIC, 16-Leads, Body 9.9x3.9mm, Pitch 1.27mm, IPC Medium Density)
footprint M16A_L (SOIC, 16-Leads, Body 9.9x3.9mm, Pitch 1.27mm, IPC High Density)
footprint M16A_M (SOIC, 16-Leads, Body 9.9x3.9mm, Pitch 1.27mm, IPC Low Density)
3D model M16A (16-Pin Small Outline Integrated Circuit 1.27 mm Pitch)
pins: 1 Y1 (io), 2 Y0 (io), 3 Z1 (io), 4 Z (io), 5 Z0 (io), 6 ~{EN} (in), 7 VEE (power), 8 GND (power), 9 C (in), 10 B (in), 11 A (in), 12 X0 (io), 13 X1 (io), 14 X (io), 15 Y (io), 16 VCC (power)

## 74VHC4053MTC
designator U?
Triple 2-Channel Analog Multiplexer
footprint MTC16_N (TSOP, 16-Leads, Body 5x4.4mm, Pitch 0.65mm, IPC Medium Density)
footprint MTC16_L (TSOP, 16-Leads, Body 5x4.4mm, Pitch 0.65mm, IPC High Density)
footprint MTC16_M (TSOP, 16-Leads, Body 5x4.4mm, Pitch 0.65mm, IPC Low Density)
3D model MTC16 (16-Pin Thin Small Outline Package 0.65 mm Pitch)
pins: 1 Y1 (io), 2 Y0 (io), 3 Z1 (io), 4 Z (io), 5 Z0 (io), 6 ~{EN} (in), 7 VEE (power), 8 GND (power), 9 C (in), 10 B (in), 11 A (in), 12 X0 (io), 13 X1 (io), 14 X (io), 15 Y (io), 16 VCC (power)

## 74VHC4053N
designator U?
Triple 2-Channnel Analog Multiplexer
footprint N16E (DIP, 16-Leads, Row Spacing 7.62mm, Pitch 2.54mm, Body 19.3x6.35mm)
3D model N16E (DIP, 16-Pin, Row Spacing 7.62 mm, Pitch 2.54 mm)
pins: 1 Y1 (io), 2 Y0 (io), 3 Z1 (io), 4 Z (io), 5 Z0 (io), 6 ~{EN} (in), 7 VEE (power), 8 GND (power), 9 C (in), 10 B (in), 11 A (in), 12 X0 (io), 13 X1 (io), 14 X (io), 15 Y (io), 16 VCC (power)

## 74VHC4053WM
designator U?
Triple 2-Channel Analog Multiplexer
footprint M16B_N (SOIC, 16-Leads, Body 10.3x7.5mm, Pitch 1.27mm, IPC Medium Density)
footprint M16B_L (SOIC, 16-Leads, Body 10.3x7.5mm, Pitch 1.27mm, IPC High Density)
footprint M16B_M (SOIC, 16-Leads, Body 10.3x7.5mm, Pitch 1.27mm, IPC Low Density)
3D model M16B (16-Pin Small Outline Integrated Circuit 1.27 mm Pitch)
pins: 1 Y1 (io), 2 Y0 (io), 3 Z1 (io), 4 Z (io), 5 Z0 (io), 6 ~{EN} (in), 7 VEE (power), 8 GND (power), 9 C (in), 10 B (in), 11 A (in), 12 X0 (io), 13 X1 (io), 14 X (io), 15 Y (io), 16 VCC (power)

## CD4051BCM
designator U?
8-Channel Analog Multiplexer/Demultiplexer
footprint M16A_N (SOIC, 16-Leads, Body 9.9x3.9mm, Pitch 1.27mm, IPC Medium Density)
footprint M16A_L (SOIC, 16-Leads, Body 9.9x3.9mm, Pitch 1.27mm, IPC High Density)
footprint M16A_M (SOIC, 16-Leads, Body 9.9x3.9mm, Pitch 1.27mm, IPC Low Density)
3D model M16A (16-Pin Small Outline Integrated Circuit 1.27 mm Pitch)
pins: 1 X4 (io), 2 X6 (io), 3 X (io), 4 X7 (io), 5 X5 (io), 6 ~{EN} (in), 7 VEE (power), 8 GND (power), 9 C (in), 10 B (in), 11 A (in), 12 X3 (io), 13 X0 (io), 14 X1 (io), 15 X2 (io), 16 VCC (power)

## CD4051BCMTC
designator U?
8-Channel Analog Multiplexer/Demultiplexer
footprint MTC16_N (TSOP, 16-Leads, Body 5x4.4mm, Pitch 0.65mm, IPC Medium Density)
footprint MTC16_L (TSOP, 16-Leads, Body 5x4.4mm, Pitch 0.65mm, IPC High Density)
footprint MTC16_M (TSOP, 16-Leads, Body 5x4.4mm, Pitch 0.65mm, IPC Low Density)
3D model MTC16 (16-Pin Thin Small Outline Package 0.65 mm Pitch)
pins: 1 X4 (io), 2 X6 (io), 3 X (io), 4 X7 (io), 5 X5 (io), 6 ~{EN} (in), 7 VEE (power), 8 GND (power), 9 C (in), 10 B (in), 11 A (in), 12 X3 (io), 13 X0 (io), 14 X1 (io), 15 X2 (io), 16 VCC (power)

## CD4051BCN
designator U?
8-Channel Analog Multiplexer/Demultiplexer
footprint N16E (DIP, 16-Leads, Row Spacing 7.62mm, Pitch 2.54mm, Body 19.3x6.35mm)
3D model N16E (DIP, 16-Pin, Row Spacing 7.62 mm, Pitch 2.54 mm)
pins: 1 X4 (io), 2 X6 (io), 3 X (io), 4 X7 (io), 5 X5 (io), 6 ~{EN} (in), 7 VEE (power), 8 GND (power), 9 C (in), 10 B (in), 11 A (in), 12 X3 (io), 13 X0 (io), 14 X1 (io), 15 X2 (io), 16 VCC (power)

## CD4052BCM
designator U?
Dual 4-Channel Analog Multiplexer/Demultiplexer
footprint M16A_N (SOIC, 16-Leads, Body 9.9x3.9mm, Pitch 1.27mm, IPC Medium Density)
footprint M16A_L (SOIC, 16-Leads, Body 9.9x3.9mm, Pitch 1.27mm, IPC High Density)
footprint M16A_M (SOIC, 16-Leads, Body 9.9x3.9mm, Pitch 1.27mm, IPC Low Density)
3D model M16A (16-Pin Small Outline Integrated Circuit 1.27 mm Pitch)
pins: 1 Y0 (io), 2 Y2 (io), 3 Y (io), 4 Y3 (io), 5 Y1 (io), 6 ~{EN} (in), 7 VEE (power), 8 GND (power), 9 B (in), 10 A (in), 11 X3 (io), 12 X0 (io), 13 X (io), 14 X1 (io), 15 X2 (io), 16 VCC (power)

## CD4052BCN
designator U?
Dual 4-Channel Analog Multiplexer/Demultiplexer
footprint N16E (DIP, 16-Leads, Row Spacing 7.62mm, Pitch 2.54mm, Body 19.3x6.35mm)
3D model N16E (DIP, 16-Pin, Row Spacing 7.62 mm, Pitch 2.54 mm)
pins: 1 Y0 (io), 2 Y2 (io), 3 Y (io), 4 Y3 (io), 5 Y1 (io), 6 ~{EN} (in), 7 VEE (power), 8 GND (power), 9 B (in), 10 A (in), 11 X3 (io), 12 X0 (io), 13 X (io), 14 X1 (io), 15 X2 (io), 16 VCC (power)

## CD4052BCSJ
designator U?
Dual 4-Channel Analog Multiplexer/Demultiplexer
footprint M16D_N (SOP, 16-Leads, Body 10.1x5.3mm, Pitch 1.27mm, IPC Medium Density)
footprint M16D_L (SOP, 16-Leads, Body 10.1x5.3mm, Pitch 1.27mm, IPC High Density)
footprint M16D_M (SOP, 16-Leads, Body 10.1x5.3mm, Pitch 1.27mm, IPC Low Density)
3D model M16D (16-Pin Small Outline Package 1.27 mm Pitch)
pins: 1 Y0 (io), 2 Y2 (io), 3 Y (io), 4 Y3 (io), 5 Y1 (io), 6 ~{EN} (in), 7 VEE (power), 8 GND (power), 9 B (in), 10 A (in), 11 X3 (io), 12 X0 (io), 13 X (io), 14 X1 (io), 15 X2 (io), 16 VCC (power)

## CD4053BCM
designator U?
Triple 2-Channnel Analog Multiplexer/Demutiplexer
footprint M16A_N (SOIC, 16-Leads, Body 9.9x3.9mm, Pitch 1.27mm, IPC Medium Density)
footprint M16A_L (SOIC, 16-Leads, Body 9.9x3.9mm, Pitch 1.27mm, IPC High Density)
footprint M16A_M (SOIC, 16-Leads, Body 9.9x3.9mm, Pitch 1.27mm, IPC Low Density)
3D model M16A (16-Pin Small Outline Integrated Circuit 1.27 mm Pitch)
pins: 1 Y1 (io), 2 Y0 (io), 3 Z1 (io), 4 Z (io), 5 Z0 (io), 6 ~{EN} (in), 7 VEE (power), 8 GND (power), 9 C (in), 10 B (in), 11 A (in), 12 X0 (io), 13 X1 (io), 14 X (io), 15 Y (io), 16 VCC (power)

## CD4053BCN
designator U?
Triple 2-Channnel Analog Multiplexer/Demutiplexer
footprint N16E (DIP, 16-Leads, Row Spacing 7.62mm, Pitch 2.54mm, Body 19.3x6.35mm)
3D model N16E (DIP, 16-Pin, Row Spacing 7.62 mm, Pitch 2.54 mm)
pins: 1 Y1 (io), 2 Y0 (io), 3 Z1 (io), 4 Z (io), 5 Z0 (io), 6 ~{EN} (in), 7 VEE (power), 8 GND (power), 9 C (in), 10 B (in), 11 A (in), 12 X0 (io), 13 X1 (io), 14 X (io), 15 Y (io), 16 VCC (power)

## CD4053BCSJ
designator U?
Triple 2-Channnel Analog Multiplexer/Demutiplexer
footprint M16D_N (SOP, 16-Leads, Body 10.1x5.3mm, Pitch 1.27mm, IPC Medium Density)
footprint M16D_L (SOP, 16-Leads, Body 10.1x5.3mm, Pitch 1.27mm, IPC High Density)
footprint M16D_M (SOP, 16-Leads, Body 10.1x5.3mm, Pitch 1.27mm, IPC Low Density)
3D model M16D (16-Pin Small Outline Package 1.27 mm Pitch)
pins: 1 Y1 (io), 2 Y0 (io), 3 Z1 (io), 4 Z (io), 5 Z0 (io), 6 ~{EN} (in), 7 VEE (power), 8 GND (power), 9 C (in), 10 B (in), 11 A (in), 12 X0 (io), 13 X1 (io), 14 X (io), 15 Y (io), 16 VCC (power)

## DM54LS253J
designator U?
3-State Data Selector/Multiplexer; Note: Generic simulation model provided.
footprint J16A (DIP, 16-Leads, Row Spacing 7.62mm, Pitch 2.54mm, Body 19.56x6.73mm)
3D model N16E (CerDIP, 16-Pin, Row Spacing 7.62 mm, Pitch 2.54 mm)
simulation model 74LS253 (SIMCODE)
signal-integrity model DM54LS253J
pins: 1 1~{OE} (in), 2 ~{B} (in), 3 1C3 (in), 4 1C2 (in), 5 1C1 (in), 6 1C0 (in), 7 Y1 (hiz), 8 GND (power), 9 Y2 (hiz), 10 2C0 (in), 11 2C1 (in), 12 2C2 (in), 13 2C3 (in), 14 ~{A} (in), 15 2~{OE} (in), 16 VDD (power)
